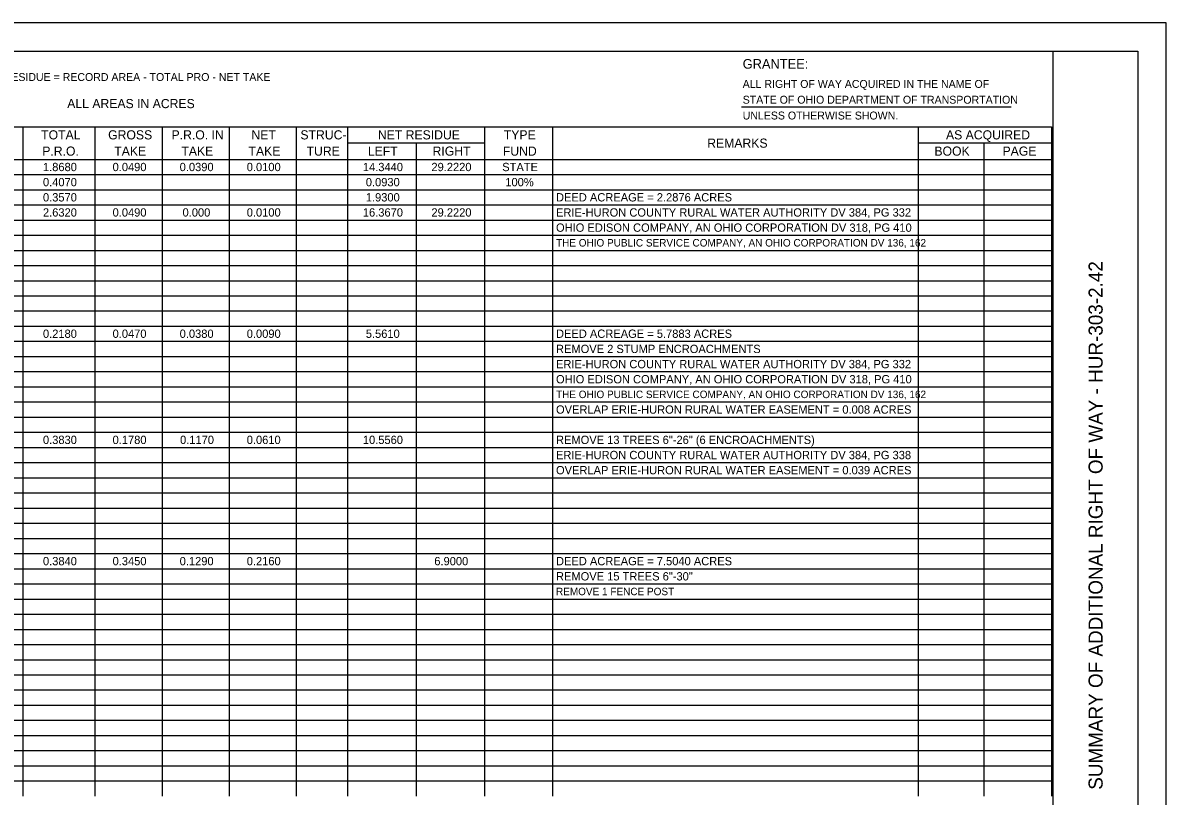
# Model space of a CAD drawing. Extents: x 0 to 34, y 0 to 22.
# Drawn here: x 13.74 to 34, y 8.3 to 22 of the extents above; entities that cross this region are included whole.
import ezdxf

# ---------------------------------------------------------------- set-up
doc = ezdxf.new("R2010")
doc.units = 0
for name, color, linetype in [('SH_Border', 7, 'Continuous'), ('SH_Cut_Line', 7, 'Continuous'), ('SH_Data', 7, 'Continuous'), ('SH_Text', 7, 'Continuous')]:
    doc.layers.add(name, color=color, linetype=linetype)

msp = doc.modelspace()

# ---------------------------------------------------------------- linework, layer by layer
at = {"layer": 'SH_Border'}
msp.add_line((32, 0.5), (32, 21.5), dxfattribs=at)
msp.add_lwpolyline([(1.5, 21.5), (33.5, 21.5), (33.5, 0.5), (1.5, 0.5)], close=True, dxfattribs=at)
at = {"layer": 'SH_Cut_Line'}
msp.add_lwpolyline([(0, 0), (34, 0), (34, 22), (0, 22)], close=True, dxfattribs=at)
at = {"layer": 'SH_Text'}
for p, q in [((26.473, 20.512), (31.253, 20.512)), ((12.599, 20.157), (13.737, 20.157)), ((13.737, 20.157), (16.205, 20.157)), ((13.737, 20.157), (13.737, 15.823)), ((15.015, 20.157), (15.015, 15.823)), ((16.205, 20.157), (30.768, 20.157)), ((16.205, 20.157), (16.205, 15.823)), ((17.394, 20.157), (17.394, 15.823)), ((18.583, 20.157), (18.583, 15.823)), ((19.491, 20.157), (19.491, 15.823)), ((21.92, 20.157), (21.92, 15.823)), ((23.122, 20.157), (23.122, 15.823)), ((29.605, 20.157), (29.605, 15.823)), ((30.768, 20.157), (31.97, 20.157)), ((31.97, 20.157), (31.97, 15.823)), ((19.491, 19.876), (21.92, 19.876)), ((20.705, 19.876), (20.705, 15.823)), ((29.605, 19.876), (30.768, 19.876)), ((30.768, 19.876), (31.97, 19.876)), ((30.768, 19.876), (30.768, 15.823)), ((12.599, 19.582), (13.737, 19.582)), ((13.737, 19.582), (16.205, 19.582)), ((16.205, 19.582), (30.768, 19.582)), ((30.768, 19.582), (31.97, 19.582)), ((12.599, 19.313), (13.737, 19.313)), ((13.737, 19.313), (16.205, 19.313)), ((16.205, 19.313), (30.768, 19.313)), ((30.768, 19.313), (31.97, 19.313)), ((12.599, 19.045), (13.737, 19.045)), ((13.737, 19.045), (16.205, 19.045)), ((16.205, 19.045), (30.768, 19.045)), ((30.768, 19.045), (31.97, 19.045)), ((12.599, 18.776), (13.737, 18.776)), ((13.737, 18.776), (16.205, 18.776)), ((16.205, 18.776), (18.583, 18.776)), ((18.583, 18.776), (19.491, 18.776)), ((19.491, 18.776), (21.92, 18.776)), ((21.92, 18.776), (30.768, 18.776)), ((30.768, 18.776), (31.97, 18.776)), ((12.599, 18.508), (13.737, 18.508)), ((13.737, 18.508), (16.205, 18.508)), ((16.205, 18.508), (30.768, 18.508)), ((30.768, 18.508), (31.97, 18.508)), ((12.599, 18.239), (13.737, 18.239)), ((13.737, 18.239), (16.205, 18.239)), ((16.205, 18.239), (30.768, 18.239)), ((30.768, 18.239), (31.97, 18.239)), ((12.599, 17.971), (13.737, 17.971)), ((13.737, 17.971), (16.205, 17.971)), ((16.205, 17.971), (30.768, 17.971)), ((30.768, 17.971), (31.97, 17.971)), ((12.599, 17.702), (13.737, 17.702)), ((13.737, 17.702), (16.205, 17.702)), ((16.205, 17.702), (30.768, 17.702)), ((30.768, 17.702), (31.97, 17.702)), ((12.599, 17.434), (13.737, 17.434)), ((13.737, 17.434), (16.205, 17.434)), ((16.205, 17.434), (30.768, 17.434)), ((30.768, 17.434), (31.97, 17.434)), ((12.599, 17.165), (13.737, 17.165)), ((13.737, 17.165), (16.205, 17.165)), ((16.205, 17.165), (30.768, 17.165)), ((30.768, 17.165), (31.97, 17.165)), ((12.599, 16.897), (13.737, 16.897)), ((13.737, 16.897), (16.205, 16.897)), ((16.205, 16.897), (30.768, 16.897)), ((30.768, 16.897), (31.97, 16.897)), ((12.599, 16.628), (13.737, 16.628)), ((13.737, 16.628), (16.205, 16.628)), ((16.205, 16.628), (30.768, 16.628)), ((30.768, 16.628), (31.97, 16.628)), ((12.599, 16.36), (13.737, 16.36)), ((13.737, 16.36), (16.205, 16.36)), ((16.205, 16.36), (30.768, 16.36)), ((30.768, 16.36), (31.97, 16.36)), ((12.599, 16.091), (13.737, 16.091)), ((13.737, 16.091), (16.205, 16.091)), ((16.205, 16.091), (30.768, 16.091)), ((30.768, 16.091), (31.97, 16.091)), ((12.599, 15.823), (13.737, 15.823)), ((13.737, 15.823), (16.205, 15.823)), ((13.737, 15.823), (13.737, 15.554)), ((15.015, 15.823), (15.015, 15.554)), ((16.205, 15.823), (30.768, 15.823)), ((16.205, 15.823), (16.205, 15.554)), ((17.394, 15.823), (17.394, 15.554)), ((18.583, 15.823), (18.583, 15.554)), ((19.491, 15.823), (19.491, 15.554)), ((20.705, 15.823), (20.705, 15.554)), ((21.92, 15.823), (21.92, 15.554)), ((23.122, 15.823), (23.122, 15.554)), ((29.605, 15.823), (29.605, 15.554)), ((30.768, 15.823), (31.97, 15.823)), ((30.768, 15.823), (30.768, 15.554)), ((31.97, 15.823), (31.97, 15.554)), ((12.599, 15.554), (13.737, 15.554)), ((13.737, 15.554), (16.205, 15.554)), ((13.737, 15.554), (13.737, 15.286)), ((15.015, 15.554), (15.015, 15.286)), ((16.205, 15.554), (30.768, 15.554)), ((16.205, 15.554), (16.205, 15.286)), ((17.394, 15.554), (17.394, 15.286)), ((18.583, 15.554), (18.583, 15.286)), ((19.491, 15.554), (19.491, 15.286)), ((20.705, 15.554), (20.705, 15.286)), ((21.92, 15.554), (21.92, 15.286)), ((23.122, 15.554), (23.122, 15.286)), ((29.605, 15.554), (29.605, 15.286)), ((30.768, 15.554), (31.97, 15.554)), ((30.768, 15.554), (30.768, 15.286)), ((31.97, 15.554), (31.97, 15.286)), ((12.599, 15.286), (13.737, 15.286)), ((13.737, 15.286), (16.205, 15.286)), ((13.737, 15.286), (13.737, 15.017)), ((15.015, 15.286), (15.015, 15.017)), ((16.205, 15.286), (30.768, 15.286)), ((16.205, 15.286), (16.205, 15.017)), ((17.394, 15.286), (17.394, 15.017)), ((18.583, 15.286), (18.583, 15.017)), ((19.491, 15.286), (19.491, 15.017)), ((20.705, 15.286), (20.705, 15.017)), ((21.92, 15.286), (21.92, 15.017)), ((23.122, 15.286), (23.122, 15.017)), ((29.605, 15.286), (29.605, 15.017)), ((30.768, 15.286), (31.97, 15.286)), ((30.768, 15.286), (30.768, 15.017)), ((31.97, 15.286), (31.97, 15.017)), ((12.599, 15.017), (13.737, 15.017)), ((13.737, 15.017), (16.205, 15.017)), ((13.737, 15.017), (13.737, 14.48)), ((15.015, 15.017), (15.015, 14.48)), ((16.205, 15.017), (30.768, 15.017)), ((16.205, 15.017), (16.205, 14.48)), ((17.394, 15.017), (17.394, 14.48)), ((18.583, 15.017), (18.583, 14.48)), ((19.491, 15.017), (19.491, 14.48)), ((20.705, 15.017), (20.705, 14.48)), ((21.92, 15.017), (21.92, 14.48)), ((23.122, 15.017), (23.122, 14.48)), ((29.605, 15.017), (29.605, 14.48)), ((30.768, 15.017), (31.97, 15.017)), ((30.768, 15.017), (30.768, 14.48)), ((31.97, 15.017), (31.97, 14.48)), ((12.599, 14.749), (13.737, 14.749)), ((13.737, 14.749), (16.205, 14.749)), ((16.205, 14.749), (30.768, 14.749)), ((30.768, 14.749), (31.97, 14.749)), ((12.599, 14.48), (13.737, 14.48)), ((13.737, 14.48), (16.205, 14.48)), ((13.737, 14.48), (13.737, 14.212)), ((15.015, 14.48), (15.015, 14.212)), ((16.205, 14.48), (30.768, 14.48)), ((16.205, 14.48), (16.205, 14.212)), ((17.394, 14.48), (17.394, 14.212)), ((18.583, 14.48), (18.583, 14.212)), ((19.491, 14.48), (19.491, 14.212)), ((20.705, 14.48), (20.705, 14.212)), ((21.92, 14.48), (21.92, 14.212)), ((23.122, 14.48), (23.122, 14.212)), ((29.605, 14.48), (29.605, 14.212)), ((30.768, 14.48), (31.97, 14.48)), ((30.768, 14.48), (30.768, 14.212)), ((31.97, 14.48), (31.97, 14.212)), ((12.599, 14.212), (13.737, 14.212)), ((13.737, 14.212), (16.205, 14.212)), ((13.737, 14.212), (13.737, 9.647)), ((15.015, 14.212), (15.015, 9.647)), ((16.205, 14.212), (30.768, 14.212)), ((16.205, 14.212), (16.205, 9.647)), ((17.394, 14.212), (17.394, 9.647)), ((18.583, 14.212), (18.583, 9.647)), ((19.491, 14.212), (19.491, 9.647)), ((20.705, 14.212), (20.705, 9.647)), ((21.92, 14.212), (21.92, 9.647)), ((23.122, 14.212), (23.122, 9.647)), ((29.605, 14.212), (29.605, 9.647)), ((30.768, 14.212), (31.97, 14.212)), ((30.768, 14.212), (30.768, 9.647)), ((31.97, 14.212), (31.97, 9.647)), ((12.599, 13.943), (13.737, 13.943)), ((13.737, 13.943), (16.205, 13.943)), ((16.205, 13.943), (30.768, 13.943)), ((30.768, 13.943), (31.97, 13.943)), ((12.599, 13.675), (13.737, 13.675)), ((13.737, 13.675), (16.205, 13.675)), ((16.205, 13.675), (30.768, 13.675)), ((30.768, 13.675), (31.97, 13.675)), ((12.599, 13.406), (13.737, 13.406)), ((13.737, 13.406), (16.205, 13.406)), ((16.205, 13.406), (30.768, 13.406)), ((30.768, 13.406), (31.97, 13.406)), ((12.599, 13.138), (13.737, 13.138)), ((13.737, 13.138), (16.205, 13.138)), ((16.205, 13.138), (30.768, 13.138)), ((30.768, 13.138), (31.97, 13.138)), ((12.599, 12.869), (13.737, 12.869)), ((13.737, 12.869), (16.205, 12.869)), ((16.205, 12.869), (30.768, 12.869)), ((30.768, 12.869), (31.97, 12.869)), ((12.599, 12.601), (13.737, 12.601)), ((13.737, 12.601), (16.205, 12.601)), ((16.205, 12.601), (30.768, 12.601)), ((30.768, 12.601), (31.97, 12.601)), ((12.599, 12.332), (13.737, 12.332)), ((13.737, 12.332), (16.205, 12.332)), ((16.205, 12.332), (30.768, 12.332)), ((30.768, 12.332), (31.97, 12.332)), ((12.599, 12.063), (13.737, 12.063)), ((13.737, 12.063), (16.205, 12.063)), ((16.205, 12.063), (30.768, 12.063)), ((30.768, 12.063), (31.97, 12.063)), ((12.599, 11.795), (13.737, 11.795)), ((13.737, 11.795), (16.205, 11.795)), ((16.205, 11.795), (30.768, 11.795)), ((30.768, 11.795), (31.97, 11.795)), ((12.599, 11.526), (13.737, 11.526)), ((13.737, 11.526), (16.205, 11.526)), ((16.205, 11.526), (30.768, 11.526)), ((30.768, 11.526), (31.97, 11.526)), ((12.599, 11.258), (13.737, 11.258)), ((13.737, 11.258), (16.205, 11.258)), ((16.205, 11.258), (30.768, 11.258)), ((30.768, 11.258), (31.97, 11.258)), ((12.599, 10.989), (13.737, 10.989)), ((13.737, 10.989), (16.205, 10.989)), ((16.205, 10.989), (30.768, 10.989)), ((30.768, 10.989), (31.97, 10.989)), ((12.599, 10.721), (13.737, 10.721)), ((13.737, 10.721), (16.205, 10.721)), ((16.205, 10.721), (30.768, 10.721)), ((30.768, 10.721), (31.97, 10.721)), ((12.599, 10.452), (13.737, 10.452)), ((13.737, 10.452), (16.205, 10.452)), ((16.205, 10.452), (30.768, 10.452)), ((30.768, 10.452), (31.97, 10.452)), ((12.599, 10.184), (13.737, 10.184)), ((13.737, 10.184), (16.205, 10.184)), ((16.205, 10.184), (30.768, 10.184)), ((30.768, 10.184), (31.97, 10.184)), ((12.599, 9.915), (13.737, 9.915)), ((13.737, 9.915), (16.205, 9.915)), ((16.205, 9.915), (30.768, 9.915)), ((30.768, 9.915), (31.97, 9.915)), ((12.599, 9.647), (13.737, 9.647)), ((13.737, 9.647), (16.205, 9.647)), ((13.737, 9.647), (13.737, 9.378)), ((15.015, 9.647), (15.015, 9.378)), ((16.205, 9.647), (30.768, 9.647)), ((16.205, 9.647), (16.205, 9.378)), ((17.394, 9.647), (17.394, 9.378)), ((18.583, 9.647), (18.583, 9.378)), ((19.491, 9.647), (19.491, 9.378)), ((20.705, 9.647), (20.705, 9.378)), ((21.92, 9.647), (21.92, 9.378)), ((23.122, 9.647), (23.122, 9.378)), ((29.605, 9.647), (29.605, 9.378)), ((30.768, 9.647), (31.97, 9.647)), ((30.768, 9.647), (30.768, 9.378)), ((31.97, 9.647), (31.97, 9.378)), ((12.599, 9.378), (13.737, 9.378)), ((13.737, 9.378), (16.205, 9.378)), ((13.737, 9.378), (13.737, 9.11)), ((15.015, 9.378), (15.015, 9.11)), ((16.205, 9.378), (30.768, 9.378)), ((16.205, 9.378), (16.205, 9.11)), ((17.394, 9.378), (17.394, 9.11)), ((18.583, 9.378), (18.583, 9.11)), ((19.491, 9.378), (19.491, 9.11)), ((20.705, 9.378), (20.705, 9.11)), ((21.92, 9.378), (21.92, 9.11)), ((23.122, 9.378), (23.122, 9.11)), ((29.605, 9.378), (29.605, 9.11)), ((30.768, 9.378), (31.97, 9.378)), ((30.768, 9.378), (30.768, 9.11)), ((31.97, 9.378), (31.97, 9.11)), ((12.599, 9.11), (13.737, 9.11)), ((13.737, 9.11), (16.205, 9.11)), ((13.737, 9.11), (13.737, 8.304)), ((15.015, 9.11), (15.015, 8.304)), ((16.205, 9.11), (30.768, 9.11)), ((16.205, 9.11), (16.205, 8.304)), ((17.394, 9.11), (17.394, 8.304)), ((18.583, 9.11), (18.583, 8.304)), ((19.491, 9.11), (19.491, 8.304)), ((20.705, 9.11), (20.705, 8.304)), ((21.92, 9.11), (21.92, 8.304)), ((23.122, 9.11), (23.122, 8.304)), ((29.605, 9.11), (29.605, 8.304)), ((30.768, 9.11), (31.97, 9.11)), ((30.768, 9.11), (30.768, 8.304)), ((31.97, 9.11), (31.97, 8.304)), ((12.599, 8.841), (13.737, 8.841)), ((13.737, 8.841), (16.205, 8.841)), ((16.205, 8.841), (30.768, 8.841)), ((30.768, 8.841), (31.97, 8.841)), ((12.599, 8.573), (13.737, 8.573)), ((13.737, 8.573), (16.205, 8.573)), ((16.205, 8.573), (30.768, 8.573)), ((30.768, 8.573), (31.97, 8.573))]:
    msp.add_line(p, q, dxfattribs=at)

# ---------------------------------------------------------------- texts
at = {"layer": 'SH_Data'}
msp.add_text('SUMMARY OF ADDITIONAL RIGHT OF WAY - HUR-303-2.42', height=0.25, rotation=90, dxfattribs=at).set_placement((32.875, 8.417))
at = {"layer": 'SH_Text'}
for s, height, p in [('GRANTEE:', 0.17, (26.495, 21.189)), ('NET RESIDUE = RECORD AREA - TOTAL PRO - NET TAKE', 0.14, (12.971, 20.971)), ('ALL RIGHT OF WAY ACQUIRED IN THE NAME OF', 0.14, (26.495, 20.849)), ('STATE OF OHIO DEPARTMENT OF TRANSPORTATION     ', 0.14, (26.495, 20.569)), ('ALL AREAS IN ACRES', 0.16175, (14.523, 20.49)), ('UNLESS OTHERWISE SHOWN.', 0.14, (26.495, 20.289)), ('TOTAL', 0.1618, (14.061, 19.936)), ('GROSS', 0.1618, (15.248, 19.936)), ('P.R.O. IN', 0.1618, (16.372, 19.936)), ('NET', 0.1618, (17.787, 19.936)), ('STRUC-', 0.1618, (18.656, 19.936)), ('NET RESIDUE', 0.16175, (20.029, 19.936)), ('TYPE', 0.1618, (22.261, 19.936)), ('AS ACQUIRED', 0.16175, (30.098, 19.936)), ('REMARKS', 0.1618, (25.866, 19.789)), ('P.R.O.', 0.1618, (14.08, 19.648)), ('TAKE', 0.1618, (15.357, 19.648)), ('TAKE', 0.1618, (16.546, 19.648)), ('TAKE', 0.1618, (17.736, 19.648)), ('TURE', 0.1618, (18.765, 19.648)), ('LEFT', 0.1618, (19.851, 19.648)), ('RIGHT', 0.1618, (20.998, 19.648)), ('FUND', 0.1618, (22.244, 19.648)), ('BOOK', 0.1618, (29.893, 19.648)), ('PAGE', 0.1618, (31.1, 19.648)), ('1.8680', 0.147, (14.093, 19.374)), ('0.0490', 0.147, (15.327, 19.374)), ('0.0390', 0.147, (16.516, 19.374)), ('0.0100', 0.147, (17.705, 19.374)), ('14.3440', 0.147, (19.763, 19.374)), ('29.2220', 0.147, (20.978, 19.374)), ('STATE', 0.147, (22.233, 19.374)), ('0.4070', 0.147, (14.093, 19.106)), ('0.0930', 0.147, (19.815, 19.106)), ('100%', 0.147, (22.288, 19.106)), ('0.3570', 0.147, (14.093, 18.837)), ('1.9300', 0.147, (19.815, 18.837)), ('DEED ACREAGE = 2.2876 ACRES', 0.14705, (23.186, 18.837)), ('2.6320', 0.147, (14.093, 18.569)), ('0.0490', 0.147, (15.327, 18.569)), ('0.000', 0.147, (16.567, 18.569)), ('0.0100', 0.147, (17.705, 18.569)), ('16.3670', 0.147, (19.763, 18.569)), ('29.2220', 0.147, (20.978, 18.569)), ('ERIE-HURON COUNTY RURAL WATER AUTHORITY DV 384, PG 332', 0.14705, (23.186, 18.569)), ('OHIO EDISON COMPANY, AN OHIO CORPORATION DV 318, PG 410', 0.14705, (23.186, 18.3)), ('THE OHIO PUBLIC SERVICE COMPANY, AN OHIO CORPORATION DV 136, 162', 0.13234, (23.186, 18.039)), ('0.2180', 0.147, (14.093, 16.421)), ('0.0470', 0.147, (15.327, 16.421)), ('0.0380', 0.147, (16.516, 16.421)), ('0.0090', 0.147, (17.705, 16.421)), ('5.5610', 0.147, (19.815, 16.421)), ('DEED ACREAGE = 5.7883 ACRES', 0.14705, (23.186, 16.421)), ('REMOVE 2 STUMP ENCROACHMENTS', 0.14705, (23.186, 16.152)), ('ERIE-HURON COUNTY RURAL WATER AUTHORITY DV 384, PG 332', 0.14705, (23.186, 15.883)), ('OHIO EDISON COMPANY, AN OHIO CORPORATION DV 318, PG 410', 0.14705, (23.186, 15.615)), ('THE OHIO PUBLIC SERVICE COMPANY, AN OHIO CORPORATION DV 136, 162', 0.13234, (23.186, 15.354)), ('OVERLAP ERIE-HURON RURAL WATER EASEMENT = 0.008 ACRES', 0.14705, (23.186, 15.078)), ('0.3830', 0.147, (14.093, 14.541)), ('0.1780', 0.147, (15.327, 14.541)), ('0.1170', 0.147, (16.523, 14.541)), ('0.0610', 0.147, (17.705, 14.541)), ('10.5560', 0.147, (19.763, 14.541)), ('REMOVE 13 TREES 6"-26" (6 ENCROACHMENTS)', 0.14705, (23.186, 14.541)), ('ERIE-HURON COUNTY RURAL WATER AUTHORITY DV 384, PG 338', 0.14705, (23.186, 14.272)), ('OVERLAP ERIE-HURON RURAL WATER EASEMENT = 0.039 ACRES', 0.14705, (23.186, 14.004)), ('0.3840', 0.147, (14.093, 12.393)), ('0.3450', 0.147, (15.327, 12.393)), ('0.1290', 0.147, (16.516, 12.393)), ('0.2160', 0.147, (17.705, 12.393)), ('6.9000', 0.147, (21.029, 12.393)), ('DEED ACREAGE = 7.5040 ACRES', 0.14705, (23.186, 12.393)), ('REMOVE 15 TREES 6"-30"', 0.14705, (23.186, 12.124)), ('REMOVE 1 FENCE POST', 0.13234, (23.186, 11.863))]:
    msp.add_text(s, height=height, dxfattribs=at).set_placement(p)

doc.saveas('drawing.dxf')
